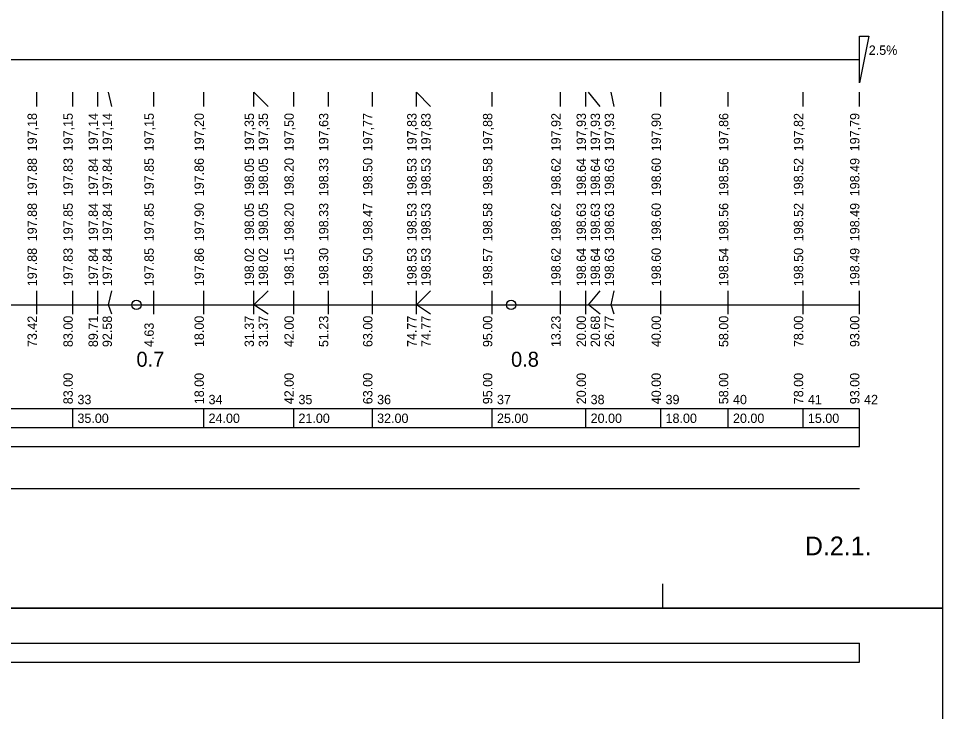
# Model space of a CAD drawing. Extents: x -51 to 53, y -74 to 15.
# Drawn here: x 28.41 to 53.08, y -47 to -28.51 of the extents above; entities that cross this region are included whole.
import ezdxf

# ---------------------------------------------------------------- set-up
doc = ezdxf.new("R2010")
doc.units = 0
for name, color, linetype in [('Implicitní', 7, 'Continuous'), ('KOTY_L', 7, 'Continuous'), ('KOTY_N', 7, 'Continuous'), ('KOTY_S', 7, 'Continuous'), ('KOTY_T', 7, 'Continuous'), ('KOTY_VP', 7, 'Continuous'), ('Nová vrstva (0)', 7, 'Continuous'), ('PR_SKLON_L', 7, 'Continuous'), ('PR_SKLON_T', 7, 'Continuous'), ('ROVINA_100', 7, 'Continuous'), ('ROVINA_L', 7, 'Continuous'), ('ROVINA_O', 7, 'Continuous'), ('SMP_L', 7, 'Continuous'), ('TABULKY_L', 7, 'Continuous'), ('TABULKY_T', 7, 'Continuous')]:
    doc.layers.add(name, color=color, linetype=linetype)

msp = doc.modelspace()

# ---------------------------------------------------------------- linework, layer by layer
at = {"layer": 'Implicitní'}
msp.add_line((45.608, -44.246), (45.608, -43.597), dxfattribs=at)
for points in [[(-51.392, -14.546), (53.079, -14.546), (53.079, -44.246), (-51.392, -44.246)], [(-51.392, -44.246), (53.079, -44.246), (53.079, -73.946), (-51.392, -73.946)]]:
    msp.add_lwpolyline(points, close=True, dxfattribs=at)
at = {"layer": 'KOTY_L'}
for p, q in [((28.902, -30.851), (28.902, -30.476)), ((29.86, -30.851), (29.86, -30.476)), ((30.531, -30.851), (30.531, -30.476)), ((30.906, -30.851), (30.818, -30.476)), ((32.023, -30.851), (32.023, -30.476)), ((33.36, -30.851), (33.36, -30.476)), ((34.697, -30.851), (34.697, -30.476)), ((35.072, -30.851), (34.697, -30.476)), ((35.76, -30.851), (35.76, -30.476)), ((36.683, -30.851), (36.683, -30.476)), ((37.86, -30.851), (37.86, -30.476)), ((39.037, -30.851), (39.037, -30.476)), ((39.412, -30.851), (39.037, -30.476)), ((41.06, -30.851), (41.06, -30.476)), ((42.883, -30.851), (42.883, -30.476)), ((43.56, -30.851), (43.56, -30.476)), ((43.935, -30.851), (43.628, -30.476)), ((44.31, -30.851), (44.237, -30.476)), ((45.56, -30.851), (45.56, -30.476)), ((47.36, -30.851), (47.36, -30.476)), ((49.36, -30.851), (49.36, -30.476)), ((50.86, -30.851), (50.86, -30.476)), ((28.902, -34.451), (28.902, -34.451)), ((29.86, -34.451), (29.86, -34.451)), ((30.531, -34.451), (30.531, -34.451)), ((30.906, -34.451), (30.906, -34.451)), ((32.023, -34.451), (32.023, -34.451)), ((33.36, -34.451), (33.36, -34.451)), ((34.697, -34.451), (34.697, -34.451)), ((35.072, -34.451), (35.072, -34.451)), ((35.76, -34.451), (35.76, -34.451)), ((36.683, -34.451), (36.683, -34.451)), ((37.86, -34.451), (37.86, -34.451)), ((39.037, -34.451), (39.037, -34.451)), ((39.412, -34.451), (39.412, -34.451)), ((41.06, -34.451), (41.06, -34.451)), ((42.883, -34.451), (42.883, -34.451)), ((43.56, -34.451), (43.56, -34.451)), ((43.935, -34.451), (43.935, -34.451)), ((44.31, -34.451), (44.31, -34.451)), ((45.56, -34.451), (45.56, -34.451)), ((47.36, -34.451), (47.36, -34.451)), ((49.36, -34.451), (49.36, -34.451)), ((50.86, -34.451), (50.86, -34.451)), ((28.902, -36.151), (28.902, -35.776)), ((29.86, -36.151), (29.86, -35.776)), ((30.531, -36.151), (30.531, -35.776)), ((30.818, -36.151), (30.906, -35.776)), ((32.023, -36.151), (32.023, -35.776)), ((33.36, -36.151), (33.36, -35.776)), ((34.697, -36.151), (34.697, -35.776)), ((34.697, -36.151), (35.072, -35.776)), ((35.76, -36.151), (35.76, -35.776)), ((36.683, -36.151), (36.683, -35.776)), ((37.86, -36.151), (37.86, -35.776)), ((39.037, -36.151), (39.037, -35.776)), ((39.037, -36.151), (39.412, -35.776)), ((41.06, -36.151), (41.06, -35.776)), ((42.883, -36.151), (42.883, -35.776)), ((43.56, -36.151), (43.56, -35.776)), ((43.628, -36.151), (43.935, -35.776)), ((44.237, -36.151), (44.31, -35.776)), ((45.56, -36.151), (45.56, -35.776)), ((47.36, -36.151), (47.36, -35.776)), ((49.36, -36.151), (49.36, -35.776)), ((50.86, -36.151), (50.86, -35.776))]:
    msp.add_line(p, q, dxfattribs=at)
at = {"layer": 'KOTY_S'}
for p, q in [((28.902, -36.401), (28.902, -36.151)), ((29.86, -36.401), (29.86, -36.151)), ((30.531, -36.401), (30.531, -36.151)), ((30.906, -36.401), (30.818, -36.151)), ((32.023, -36.401), (32.023, -36.151)), ((33.36, -36.401), (33.36, -36.151)), ((34.697, -36.401), (34.697, -36.151)), ((35.072, -36.401), (34.697, -36.151)), ((35.76, -36.401), (35.76, -36.151)), ((36.683, -36.401), (36.683, -36.151)), ((37.86, -36.401), (37.86, -36.151)), ((39.037, -36.401), (39.037, -36.151)), ((39.412, -36.401), (39.037, -36.151)), ((41.06, -36.401), (41.06, -36.151)), ((42.883, -36.401), (42.883, -36.151)), ((43.56, -36.401), (43.56, -36.151)), ((43.935, -36.401), (43.628, -36.151)), ((44.31, -36.401), (44.237, -36.151)), ((45.56, -36.401), (45.56, -36.151)), ((47.36, -36.401), (47.36, -36.151)), ((49.36, -36.401), (49.36, -36.151)), ((50.86, -36.401), (50.86, -36.151))]:
    msp.add_line(p, q, dxfattribs=at)
at = {"layer": 'PR_SKLON_L'}
msp.add_line((8.36, -29.601), (50.86, -29.601), dxfattribs=at)
msp.add_lwpolyline([(50.86, -29.601), (50.86, -28.976), (51.11, -28.976), (50.86, -30.226)], close=True, dxfattribs=at)
at = {"layer": 'ROVINA_L'}
msp.add_line((-38.44, -36.151), (50.86, -36.151), dxfattribs=at)
at = {"layer": 'ROVINA_O'}
for centre in [(31.56, -36.151), (41.56, -36.151)]:
    msp.add_circle(centre, 0.125, dxfattribs=at)
at = {"layer": 'SMP_L'}
msp.add_line((24.26, -41.051), (50.86, -41.051), dxfattribs=at)
at = {"layer": 'TABULKY_L'}
for p, q in [((50.86, -38.926), (-38.44, -38.926)), ((29.86, -39.426), (29.86, -38.926)), ((33.36, -39.426), (33.36, -38.926)), ((35.76, -39.426), (35.76, -38.926)), ((37.86, -39.426), (37.86, -38.926)), ((41.06, -39.426), (41.06, -38.926)), ((43.56, -39.426), (43.56, -38.926)), ((45.56, -39.426), (45.56, -38.926)), ((47.36, -39.426), (47.36, -38.926)), ((49.36, -39.426), (49.36, -38.926)), ((50.86, -39.426), (50.86, -38.926)), ((50.86, -39.926), (50.86, -38.926)), ((-38.44, -39.426), (50.86, -39.426)), ((50.86, -39.926), (50.86, -39.426)), ((-38.44, -39.926), (50.86, -39.926)), ((-38.44, -45.182), (50.86, -45.182)), ((50.86, -45.682), (50.86, -45.182)), ((-38.44, -45.682), (50.86, -45.682))]:
    msp.add_line(p, q, dxfattribs=at)

# ---------------------------------------------------------------- texts
at = {"layer": 'Implicitní'}
msp.add_text('D.2.1.', height=0.5, dxfattribs=at).set_placement((49.402, -42.833))
at = {"layer": 'KOTY_N'}
for s, p in [('197.88', (28.902, -34.451)), ('197.85', (29.86, -34.451)), ('197.84', (30.531, -34.451)), ('197.84', (30.906, -34.451)), ('197.85', (32.023, -34.451)), ('197.90', (33.36, -34.451)), ('198.05', (34.697, -34.451)), ('198.05', (35.072, -34.451)), ('198.20', (35.76, -34.451)), ('198.33', (36.683, -34.451)), ('198.47', (37.86, -34.451)), ('198.53', (39.037, -34.451)), ('198.53', (39.412, -34.451)), ('198.58', (41.06, -34.451)), ('198.62', (42.883, -34.451)), ('198.63', (43.56, -34.451)), ('198.63', (43.935, -34.451)), ('198.63', (44.31, -34.451)), ('198.60', (45.56, -34.451)), ('198.56', (47.36, -34.451)), ('198.52', (49.36, -34.451)), ('198.49', (50.86, -34.451))]:
    msp.add_text(s, height=0.25, rotation=90, dxfattribs=at).set_placement(p)
at = {"layer": 'KOTY_S'}
for s, p in [('73.42', (28.902, -37.276)), ('83.00', (29.86, -37.276)), ('89.71', (30.531, -37.276)), ('92.58', (30.906, -37.276)), ('18.00', (33.36, -37.276)), ('31.37', (34.697, -37.276)), ('31.37', (35.072, -37.276)), ('42.00', (35.76, -37.276)), ('51.23', (36.683, -37.276)), ('63.00', (37.86, -37.276)), ('74.77', (39.037, -37.276)), ('74.77', (39.412, -37.276)), ('95.00', (41.06, -37.276)), ('13.23', (42.883, -37.276)), ('20.00', (43.56, -37.276)), ('20.68', (43.935, -37.276)), ('26.77', (44.31, -37.276)), ('40.00', (45.56, -37.276)), ('58.00', (47.36, -37.276)), ('78.00', (49.36, -37.276)), ('93.00', (50.86, -37.276)), ('4.63', (32.023, -37.276))]:
    msp.add_text(s, height=0.25, rotation=90, dxfattribs=at).set_placement(p)
at = {"layer": 'KOTY_T'}
for s, p in [('197.88', (28.902, -35.651)), ('197.83', (29.86, -35.651)), ('197.84', (30.531, -35.651)), ('197.84', (30.906, -35.651)), ('197.85', (32.023, -35.651)), ('197.86', (33.36, -35.651)), ('198.02', (34.697, -35.651)), ('198.02', (35.072, -35.651)), ('198.15', (35.76, -35.651)), ('198.30', (36.683, -35.651)), ('198.50', (37.86, -35.651)), ('198.53', (39.037, -35.651)), ('198.53', (39.412, -35.651)), ('198.57', (41.06, -35.651)), ('198.62', (42.883, -35.651)), ('198.64', (43.56, -35.651)), ('198.64', (43.935, -35.651)), ('198.63', (44.31, -35.651)), ('198.60', (45.56, -35.651)), ('198.54', (47.36, -35.651)), ('198.50', (49.36, -35.651)), ('198.49', (50.86, -35.651))]:
    msp.add_text(s, height=0.25, rotation=90, dxfattribs=at).set_placement(p)
at = {"layer": 'KOTY_VP'}
for s, p in [('197.88', (28.902, -33.251)), ('197.83', (29.86, -33.251)), ('197.84', (30.531, -33.251)), ('197.84', (30.906, -33.251)), ('197.85', (32.023, -33.251)), ('197.86', (33.36, -33.251)), ('198.05', (34.697, -33.251)), ('198.05', (35.072, -33.251)), ('198.20', (35.76, -33.251)), ('198.33', (36.683, -33.251)), ('198.50', (37.86, -33.251)), ('198.53', (39.037, -33.251)), ('198.53', (39.412, -33.251)), ('198.58', (41.06, -33.251)), ('198.62', (42.883, -33.251)), ('198.64', (43.56, -33.251)), ('198.64', (43.935, -33.251)), ('198.63', (44.31, -33.251)), ('198.60', (45.56, -33.251)), ('198.56', (47.36, -33.251)), ('198.52', (49.36, -33.251)), ('198.49', (50.86, -33.251))]:
    msp.add_text(s, height=0.25, rotation=90, dxfattribs=at).set_placement(p)
at = {"layer": 'Nová vrstva (0)'}
for s, p in [('197,18', (28.902, -32.051)), ('197,15', (29.86, -32.051)), ('197,14', (30.531, -32.051)), ('197,14', (30.906, -32.051)), ('197,15', (32.023, -32.051)), ('197,20', (33.36, -32.051)), ('197,35', (34.697, -32.051)), ('197,35', (35.072, -32.051)), ('197,50', (35.76, -32.051)), ('197,63', (36.683, -32.051)), ('197,77', (37.86, -32.051)), ('197,83', (39.037, -32.051)), ('197,83', (39.412, -32.051)), ('197,88', (41.06, -32.051)), ('197,92', (42.883, -32.051)), ('197,93', (43.56, -32.051)), ('197,93', (43.935, -32.051)), ('197,93', (44.31, -32.051)), ('197,90', (45.56, -32.051)), ('197,86', (47.36, -32.051)), ('197,82', (49.36, -32.051)), ('197,79', (50.86, -32.051))]:
    msp.add_text(s, height=0.25, rotation=90, dxfattribs=at).set_placement(p)
at = {"layer": 'PR_SKLON_T'}
msp.add_text('2.5%', height=0.25, dxfattribs=at).set_placement((51.11, -29.476))
at = {"layer": 'ROVINA_100'}
for s, p in [('0.7', (31.56, -37.801)), ('0.8', (41.56, -37.801))]:
    msp.add_text(s, height=0.4, dxfattribs=at).set_placement(p)
at = {"layer": 'TABULKY_T'}
for s, p in [('83.00', (29.86, -38.801)), ('18.00', (33.36, -38.801)), ('42.00', (35.76, -38.801)), ('63.00', (37.86, -38.801)), ('95.00', (41.06, -38.801)), ('20.00', (43.56, -38.801)), ('40.00', (45.56, -38.801)), ('58.00', (47.36, -38.801)), ('78.00', (49.36, -38.801)), ('93.00', (50.86, -38.801))]:
    msp.add_text(s, height=0.25, rotation=90, dxfattribs=at).set_placement(p)
for s, p in [('33', (29.985, -38.801)), ('34', (33.485, -38.801)), ('35', (35.885, -38.801)), ('36', (37.985, -38.801)), ('37', (41.185, -38.801)), ('38', (43.685, -38.801)), ('39', (45.685, -38.801)), ('40', (47.485, -38.801)), ('41', (49.485, -38.801)), ('42', (50.985, -38.801)), ('35.00', (29.985, -39.301)), ('24.00', (33.485, -39.301)), ('21.00', (35.885, -39.301)), ('32.00', (37.985, -39.301)), ('25.00', (41.185, -39.301)), ('20.00', (43.685, -39.301)), ('18.00', (45.685, -39.301)), ('20.00', (47.485, -39.301)), ('15.00', (49.485, -39.301))]:
    msp.add_text(s, height=0.25, dxfattribs=at).set_placement(p)

doc.saveas('drawing.dxf')
